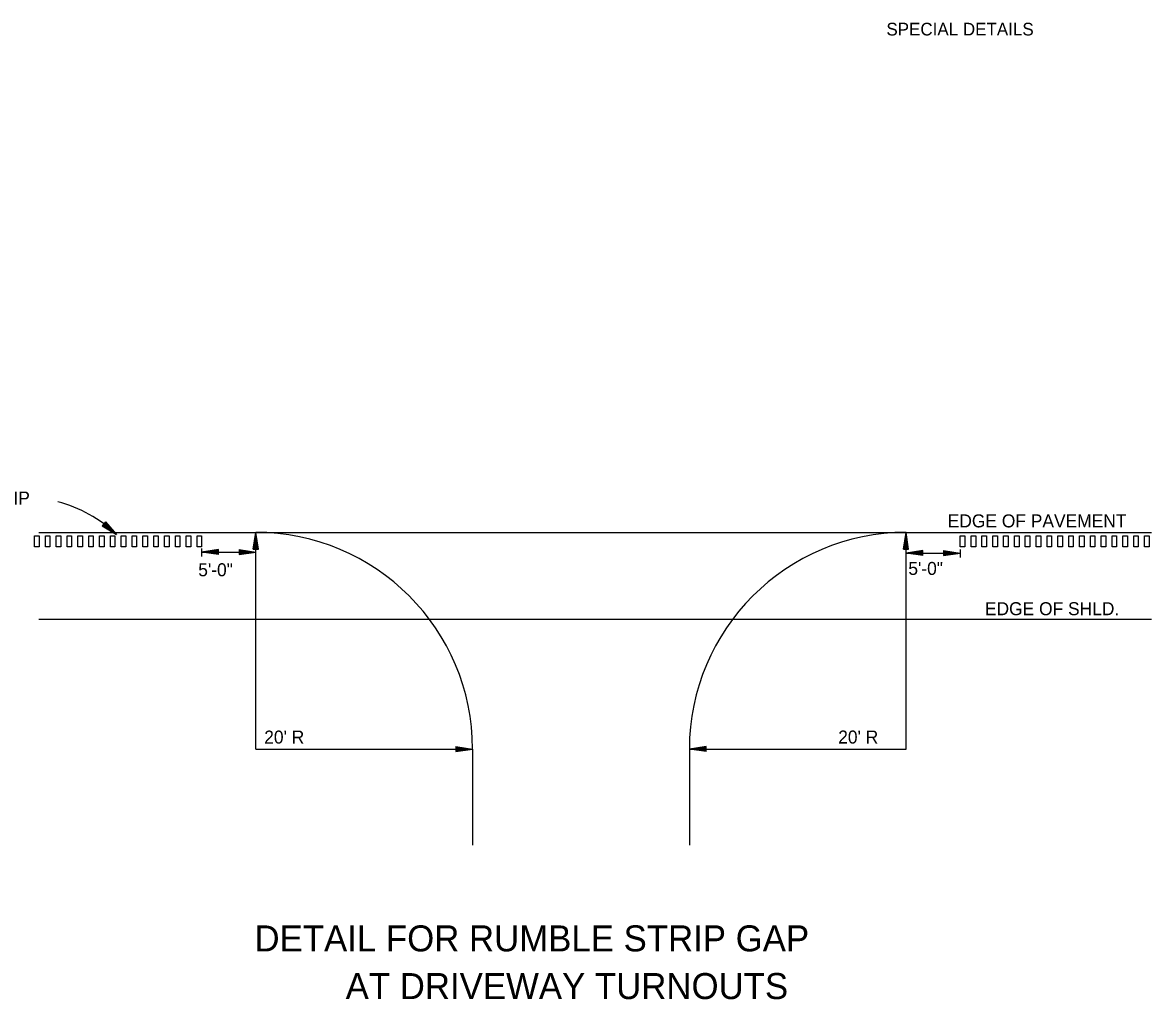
# Model space of a CAD drawing. Extents: x 1931522 to 1935523, y 600380 to 605075.
# Drawn here: x 1933743 to 1934264, y 600915 to 601366 of the extents above; entities that cross this region are included whole.
import ezdxf

# ---------------------------------------------------------------- set-up
doc = ezdxf.new("R2010")
doc.units = 0
for name, color, linetype in [('R_Border Prem', 7, 'Continuous'), ('R_Dimension', 7, 'Continuous'), ('R_Draft', 7, 'Continuous')]:
    doc.layers.add(name, color=color, linetype=linetype)

msp = doc.modelspace()

# ---------------------------------------------------------------- linework, layer by layer
at = {"layer": 'R_Dimension'}
for p, q in [((1933781.1, 601135.19), (1933779.6, 601133.41)), ((1933779.6, 601133.41), (1933786.28, 601129.31)), ((1933779.73, 601133.56), (1933785.29, 601130.15)), ((1933779.85, 601133.71), (1933784.27, 601131)), ((1933779.98, 601133.85), (1933783.28, 601131.83)), ((1933780.1, 601134.01), (1933782.28, 601132.68)), ((1933780.23, 601134.16), (1933781.29, 601133.51)), ((1933780.47, 601134.44), (1933781.29, 601133.51)), ((1933780.59, 601134.58), (1933782.28, 601132.68)), ((1933780.72, 601134.74), (1933783.28, 601131.83)), ((1933780.84, 601134.89), (1933784.27, 601131)), ((1933780.97, 601135.04), (1933785.29, 601130.15)), ((1933781.1, 601135.19), (1933786.28, 601129.31)), ((1933849.35, 601122.59), (1933850.51, 601130.33)), ((1933849.35, 601122.59), (1933850.51, 601130.33)), ((1933849.55, 601122.59), (1933850.51, 601129.04)), ((1933849.55, 601122.59), (1933850.51, 601129.04)), ((1933849.74, 601122.59), (1933850.51, 601127.71)), ((1933849.74, 601122.59), (1933850.51, 601127.71)), ((1933851.68, 601122.59), (1933850.51, 601130.33)), ((1933851.68, 601122.59), (1933850.51, 601130.33)), ((1933851.48, 601122.59), (1933850.51, 601129.04)), ((1933851.48, 601122.59), (1933850.51, 601129.04)), ((1933851.28, 601122.59), (1933850.51, 601127.71)), ((1933851.28, 601122.59), (1933850.51, 601127.71)), ((1934149.4, 601122.59), (1934150.56, 601130.33)), ((1934149.4, 601122.59), (1934150.56, 601130.33)), ((1934149.59, 601122.59), (1934150.56, 601129.04)), ((1934149.59, 601122.59), (1934150.56, 601129.04)), ((1934149.79, 601122.59), (1934150.56, 601127.71)), ((1934149.79, 601122.59), (1934150.56, 601127.71)), ((1934151.72, 601122.59), (1934150.56, 601130.33)), ((1934151.72, 601122.59), (1934150.56, 601130.33)), ((1934151.53, 601122.59), (1934150.56, 601129.04)), ((1934151.53, 601122.59), (1934150.56, 601129.04)), ((1934151.33, 601122.59), (1934150.56, 601127.71)), ((1934151.33, 601122.59), (1934150.56, 601127.71)), ((1933833.26, 601122.41), (1933825.51, 601121.25)), ((1933833.26, 601122.22), (1933826.81, 601121.25)), ((1933833.26, 601120.09), (1933833.26, 601122.41)), ((1933842.77, 601122.41), (1933850.51, 601121.25)), ((1933842.77, 601122.41), (1933842.77, 601120.09)), ((1933842.77, 601122.22), (1933849.22, 601121.25)), ((1933849.35, 601122.59), (1933851.68, 601122.59)), ((1933849.35, 601122.59), (1933851.68, 601122.59)), ((1933849.94, 601122.59), (1933850.51, 601126.42)), ((1933849.94, 601122.59), (1933850.51, 601126.42)), ((1933850.14, 601122.59), (1933850.51, 601125.11)), ((1933850.14, 601122.59), (1933850.51, 601125.11)), ((1933850.33, 601122.59), (1933850.51, 601123.81)), ((1933850.33, 601122.59), (1933850.51, 601123.81)), ((1933851.09, 601122.59), (1933850.51, 601126.42)), ((1933851.09, 601122.59), (1933850.51, 601126.42)), ((1933850.89, 601122.59), (1933850.51, 601125.11)), ((1933850.89, 601122.59), (1933850.51, 601125.11)), ((1933850.7, 601122.59), (1933850.51, 601123.81)), ((1933850.7, 601122.59), (1933850.51, 601123.81)), ((1934149.4, 601122.59), (1934151.72, 601122.59)), ((1934149.4, 601122.59), (1934151.72, 601122.59)), ((1934149.98, 601122.59), (1934150.56, 601126.42)), ((1934149.98, 601122.59), (1934150.56, 601126.42)), ((1934150.19, 601122.59), (1934150.56, 601125.11)), ((1934150.19, 601122.59), (1934150.56, 601125.11)), ((1934150.38, 601122.59), (1934150.56, 601123.81)), ((1934150.38, 601122.59), (1934150.56, 601123.81)), ((1934151.14, 601122.59), (1934150.56, 601126.42)), ((1934151.14, 601122.59), (1934150.56, 601126.42)), ((1934150.94, 601122.59), (1934150.56, 601125.11)), ((1934150.94, 601122.59), (1934150.56, 601125.11)), ((1934150.74, 601122.59), (1934150.56, 601123.81)), ((1934150.74, 601122.59), (1934150.56, 601123.81)), ((1933833.26, 601120.09), (1933825.51, 601121.25)), ((1933833.26, 601120.28), (1933826.81, 601121.25)), ((1933833.26, 601122.02), (1933828.14, 601121.25)), ((1933833.26, 601120.48), (1933828.14, 601121.25)), ((1933833.26, 601121.82), (1933829.43, 601121.25)), ((1933833.26, 601120.67), (1933829.43, 601121.25)), ((1933833.26, 601121.63), (1933830.74, 601121.25)), ((1933833.26, 601120.87), (1933830.74, 601121.25)), ((1933833.26, 601121.43), (1933832.03, 601121.25)), ((1933833.26, 601121.07), (1933832.03, 601121.25)), ((1933842.77, 601122.02), (1933847.89, 601121.25)), ((1933842.77, 601121.82), (1933846.6, 601121.25)), ((1933842.77, 601121.62), (1933845.29, 601121.25)), ((1933842.77, 601121.43), (1933843.99, 601121.25)), ((1933842.77, 601120.09), (1933850.51, 601121.25)), ((1933842.77, 601120.87), (1933845.29, 601121.25)), ((1933842.77, 601120.48), (1933847.89, 601121.25)), ((1933842.77, 601120.28), (1933849.22, 601121.25)), ((1933842.77, 601120.67), (1933846.6, 601121.25)), ((1933842.77, 601121.07), (1933843.99, 601121.25)), ((1934158.31, 601121.95), (1934150.56, 601120.79)), ((1934158.31, 601119.63), (1934150.56, 601120.79)), ((1934158.31, 601121.76), (1934151.85, 601120.79)), ((1934158.31, 601119.82), (1934151.85, 601120.79)), ((1934158.31, 601121.56), (1934153.19, 601120.79)), ((1934158.31, 601120.02), (1934153.19, 601120.79)), ((1934158.31, 601121.37), (1934154.48, 601120.79)), ((1934158.31, 601120.22), (1934154.48, 601120.79)), ((1934158.31, 601121.17), (1934155.79, 601120.79)), ((1934158.31, 601120.42), (1934155.79, 601120.79)), ((1934158.31, 601120.97), (1934157.08, 601120.79)), ((1934158.31, 601120.61), (1934157.08, 601120.79)), ((1934158.31, 601119.63), (1934158.31, 601121.95)), ((1934167.82, 601121.95), (1934175.56, 601120.79)), ((1934167.82, 601121.95), (1934167.82, 601119.63)), ((1934167.82, 601121.76), (1934174.27, 601120.79)), ((1934167.82, 601121.56), (1934172.94, 601120.79)), ((1934167.82, 601121.37), (1934171.65, 601120.79)), ((1934167.82, 601121.17), (1934170.33, 601120.79)), ((1934167.82, 601120.97), (1934169.04, 601120.79)), ((1934167.82, 601119.63), (1934175.56, 601120.79)), ((1934167.82, 601120.41), (1934170.33, 601120.79)), ((1934167.82, 601120.02), (1934172.94, 601120.79)), ((1934167.82, 601119.82), (1934174.27, 601120.79)), ((1934167.82, 601120.22), (1934171.65, 601120.79)), ((1934167.82, 601120.61), (1934169.04, 601120.79)), ((1933942.79, 601031.48), (1933950.53, 601030.32)), ((1933942.79, 601031.48), (1933942.79, 601029.16)), ((1933942.79, 601031.48), (1933950.53, 601030.32)), ((1933942.79, 601031.48), (1933942.79, 601029.16)), ((1933942.79, 601031.29), (1933949.24, 601030.32)), ((1933942.79, 601031.29), (1933949.24, 601030.32)), ((1933942.79, 601031.09), (1933947.9, 601030.32)), ((1933942.79, 601031.09), (1933947.9, 601030.32)), ((1933942.79, 601030.9), (1933946.61, 601030.32)), ((1933942.79, 601030.9), (1933946.61, 601030.32)), ((1933942.79, 601030.69), (1933945.3, 601030.32)), ((1933942.79, 601030.69), (1933945.3, 601030.32)), ((1933942.79, 601030.5), (1933944.01, 601030.32)), ((1933942.79, 601030.5), (1933944.01, 601030.32)), ((1933942.79, 601029.16), (1933950.53, 601030.32)), ((1933942.79, 601029.94), (1933945.3, 601030.32)), ((1933942.79, 601029.55), (1933947.9, 601030.32)), ((1933942.79, 601029.35), (1933949.24, 601030.32)), ((1933942.79, 601029.74), (1933946.61, 601030.32)), ((1933942.79, 601030.14), (1933944.01, 601030.32)), ((1933942.79, 601029.16), (1933950.53, 601030.32)), ((1933942.79, 601029.94), (1933945.3, 601030.32)), ((1933942.79, 601029.55), (1933947.9, 601030.32)), ((1933942.79, 601029.35), (1933949.24, 601030.32)), ((1933942.79, 601029.74), (1933946.61, 601030.32)), ((1933942.79, 601030.14), (1933944.01, 601030.32)), ((1934058.29, 601031.48), (1934050.55, 601030.32)), ((1934058.29, 601031.48), (1934050.55, 601030.32)), ((1934058.29, 601029.16), (1934050.55, 601030.32)), ((1934058.29, 601029.16), (1934050.55, 601030.32)), ((1934058.29, 601031.29), (1934051.84, 601030.32)), ((1934058.29, 601031.29), (1934051.84, 601030.32)), ((1934058.29, 601029.35), (1934051.84, 601030.32)), ((1934058.29, 601029.35), (1934051.84, 601030.32)), ((1934058.29, 601031.09), (1934053.17, 601030.32)), ((1934058.29, 601031.09), (1934053.17, 601030.32)), ((1934058.29, 601029.55), (1934053.17, 601030.32)), ((1934058.29, 601029.55), (1934053.17, 601030.32)), ((1934058.29, 601030.9), (1934054.46, 601030.32)), ((1934058.29, 601030.9), (1934054.46, 601030.32)), ((1934058.29, 601029.74), (1934054.46, 601030.32)), ((1934058.29, 601029.74), (1934054.46, 601030.32)), ((1934058.29, 601030.7), (1934055.77, 601030.32)), ((1934058.29, 601030.7), (1934055.77, 601030.32)), ((1934058.29, 601029.94), (1934055.77, 601030.32)), ((1934058.29, 601029.94), (1934055.77, 601030.32)), ((1934058.29, 601030.5), (1934057.07, 601030.32)), ((1934058.29, 601030.5), (1934057.07, 601030.32)), ((1934058.29, 601030.14), (1934057.07, 601030.32)), ((1934058.29, 601030.14), (1934057.07, 601030.32)), ((1934058.29, 601029.16), (1934058.29, 601031.48)), ((1934058.29, 601029.16), (1934058.29, 601031.48))]:
    msp.add_line(p, q, dxfattribs=at)
at = {"layer": 'R_Draft'}
for p, q in [((1933750.34, 601130.33), (1934263.74, 601130.33)), ((1933850.51, 601030.32), (1933850.51, 601130.33)), ((1934150.56, 601030.32), (1934150.56, 601130.33)), ((1933825.51, 601122.97), (1933825.51, 601119.27)), ((1934175.56, 601122.51), (1934175.56, 601118.81)), ((1933825.51, 601121.25), (1933850.51, 601121.25)), ((1934150.56, 601120.79), (1934175.56, 601120.79)), ((1933750.34, 601090.33), (1934263.74, 601090.33)), ((1933850.51, 601030.32), (1933950.53, 601030.32)), ((1933950.53, 601030.32), (1933950.53, 600986.03)), ((1934050.55, 601030.32), (1934050.55, 600986.03)), ((1934050.55, 601030.32), (1934150.56, 601030.32))]:
    msp.add_line(p, q, dxfattribs=at)
for points in [[(1933748.43, 601123.67), (1933748.43, 601128.67), (1933750.51, 601128.67), (1933750.51, 601123.67), (1933748.43, 601123.67)], [(1933753.43, 601123.67), (1933753.43, 601128.67), (1933755.51, 601128.67), (1933755.51, 601123.67), (1933753.43, 601123.67)], [(1933758.43, 601123.67), (1933758.43, 601128.67), (1933760.51, 601128.67), (1933760.51, 601123.67), (1933758.43, 601123.67)], [(1933763.43, 601123.67), (1933763.43, 601128.67), (1933765.51, 601128.67), (1933765.51, 601123.67), (1933763.43, 601123.67)], [(1933768.43, 601123.67), (1933768.43, 601128.67), (1933770.51, 601128.67), (1933770.51, 601123.67), (1933768.43, 601123.67)], [(1933773.43, 601123.67), (1933773.43, 601128.67), (1933775.51, 601128.67), (1933775.51, 601123.67), (1933773.43, 601123.67)], [(1933778.43, 601123.67), (1933778.43, 601128.67), (1933780.51, 601128.67), (1933780.51, 601123.67), (1933778.43, 601123.67)], [(1933783.43, 601123.67), (1933783.43, 601128.67), (1933785.51, 601128.67), (1933785.51, 601123.67), (1933783.43, 601123.67)], [(1933788.43, 601123.67), (1933788.43, 601128.67), (1933790.51, 601128.67), (1933790.51, 601123.67), (1933788.43, 601123.67)], [(1933793.43, 601123.67), (1933793.43, 601128.67), (1933795.51, 601128.67), (1933795.51, 601123.67), (1933793.43, 601123.67)], [(1933798.43, 601123.67), (1933798.43, 601128.67), (1933800.51, 601128.67), (1933800.51, 601123.67), (1933798.43, 601123.67)], [(1933803.43, 601123.67), (1933803.43, 601128.67), (1933805.51, 601128.67), (1933805.51, 601123.67), (1933803.43, 601123.67)], [(1933808.43, 601123.67), (1933808.43, 601128.67), (1933810.51, 601128.67), (1933810.51, 601123.67), (1933808.43, 601123.67)], [(1933813.43, 601123.67), (1933813.43, 601128.67), (1933815.51, 601128.67), (1933815.51, 601123.67), (1933813.43, 601123.67)], [(1933818.43, 601123.67), (1933818.43, 601128.67), (1933820.51, 601128.67), (1933820.51, 601123.67), (1933818.43, 601123.67)], [(1933823.43, 601123.67), (1933823.43, 601128.67), (1933825.51, 601128.67), (1933825.51, 601123.67), (1933823.43, 601123.67)], [(1934175.56, 601123.67), (1934175.56, 601128.67), (1934177.64, 601128.67), (1934177.64, 601123.67), (1934175.56, 601123.67)], [(1934180.56, 601123.67), (1934180.56, 601128.67), (1934182.65, 601128.67), (1934182.65, 601123.67), (1934180.56, 601123.67)], [(1934185.56, 601123.67), (1934185.56, 601128.67), (1934187.65, 601128.67), (1934187.65, 601123.67), (1934185.56, 601123.67)], [(1934190.56, 601123.67), (1934190.56, 601128.67), (1934192.65, 601128.67), (1934192.65, 601123.67), (1934190.56, 601123.67)], [(1934195.56, 601123.67), (1934195.56, 601128.67), (1934197.65, 601128.67), (1934197.65, 601123.67), (1934195.56, 601123.67)], [(1934200.56, 601123.67), (1934200.56, 601128.67), (1934202.65, 601128.67), (1934202.65, 601123.67), (1934200.56, 601123.67)], [(1934205.56, 601123.67), (1934205.56, 601128.67), (1934207.65, 601128.67), (1934207.65, 601123.67), (1934205.56, 601123.67)], [(1934210.56, 601123.67), (1934210.56, 601128.67), (1934212.65, 601128.67), (1934212.65, 601123.67), (1934210.56, 601123.67)], [(1934215.56, 601123.67), (1934215.56, 601128.67), (1934217.65, 601128.67), (1934217.65, 601123.67), (1934215.56, 601123.67)], [(1934220.56, 601123.67), (1934220.56, 601128.67), (1934222.65, 601128.67), (1934222.65, 601123.67), (1934220.56, 601123.67)], [(1934225.56, 601123.67), (1934225.56, 601128.67), (1934227.65, 601128.67), (1934227.65, 601123.67), (1934225.56, 601123.67)], [(1934230.56, 601123.67), (1934230.56, 601128.67), (1934232.65, 601128.67), (1934232.65, 601123.67), (1934230.56, 601123.67)], [(1934235.56, 601123.67), (1934235.56, 601128.67), (1934237.65, 601128.67), (1934237.65, 601123.67), (1934235.56, 601123.67)], [(1934240.56, 601123.67), (1934240.56, 601128.67), (1934242.65, 601128.67), (1934242.65, 601123.67), (1934240.56, 601123.67)], [(1934245.56, 601123.67), (1934245.56, 601128.67), (1934247.65, 601128.67), (1934247.65, 601123.67), (1934245.56, 601123.67)], [(1934250.56, 601123.67), (1934250.56, 601128.67), (1934252.65, 601128.67), (1934252.65, 601123.67), (1934250.56, 601123.67)], [(1934255.56, 601123.67), (1934255.56, 601128.67), (1934257.65, 601128.67), (1934257.65, 601123.67), (1934255.56, 601123.67)], [(1934260.56, 601123.67), (1934260.56, 601128.67), (1934262.65, 601128.67), (1934262.65, 601123.67), (1934260.56, 601123.67)]]:
    msp.add_lwpolyline(points, dxfattribs=at)
for centre, radius, start, end in [((1933743.22, 601084.01), 62.5, 46.4613, 75.2786), ((1933850.51, 601030.32), 100.02, 0, 90), ((1934150.56, 601030.32), 100.02, 90, 180)]:
    msp.add_arc(centre, radius, start, end, dxfattribs=at)

# ---------------------------------------------------------------- texts
at = {"layer": 'R_Border Prem'}
msp.add_text('SPECIAL DETAILS', height=5.862, rotation=360, dxfattribs=at).set_placement((1934141.45, 601359.61))
at = {"layer": 'R_Draft'}
for s, height, p in [('RUMBLE STRIP', 6.0002, (1933686.95, 601143.19)), ('EDGE OF PAVEMENT', 6.0002, (1934169.75, 601132.64)), ('5\'-0"', 6, (1933823.95, 601110.09)), ('5\'-0"', 6, (1934151.58, 601110.69)), ('EDGE OF SHLD.', 6.0002, (1934186.92, 601092.12)), ("20' R", 6, (1933854.39, 601032.88)), ("20' R", 6, (1934119.22, 601032.9)), ('DETAIL FOR RUMBLE STRIP GAP', 12.0003, (1933849.9, 600937)), ('AT DRIVEWAY TURNOUTS', 12.0003, (1933891.96, 600915))]:
    msp.add_text(s, height=height, dxfattribs=at).set_placement(p)

doc.saveas('drawing.dxf')
